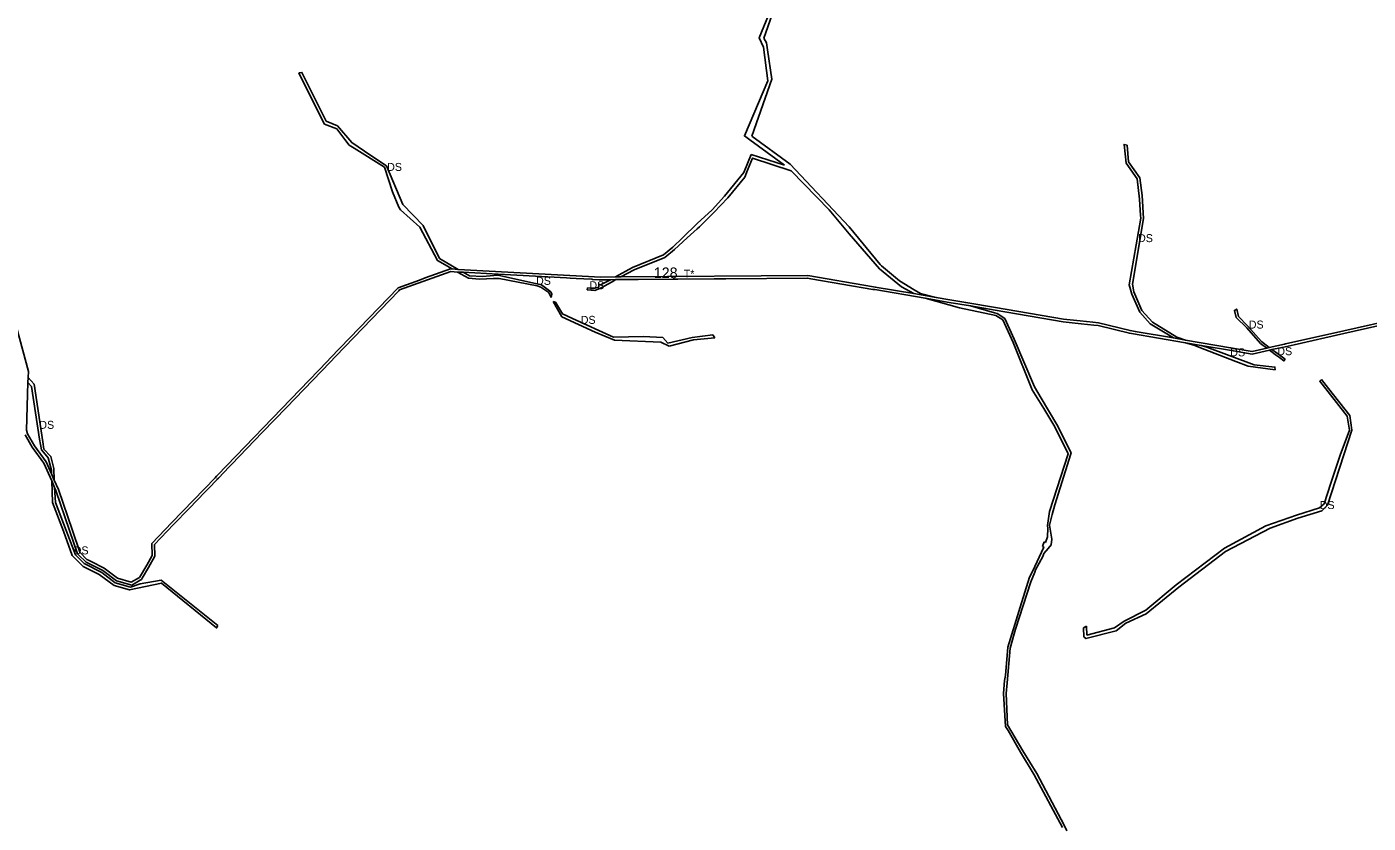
# Model space of a CAD drawing. Extents: x -477304 to -465641, y -1159113 to -1149285.
# Drawn here: x -473942 to -472433, y -1157333 to -1156437 of the extents above; entities that cross this region are included whole.
import ezdxf

# ---------------------------------------------------------------- set-up
doc = ezdxf.new("R2010")
doc.units = 0
for name, color, linetype in [('35', 7, 'Continuous'), ('4', 7, 'Continuous'), ('60', 7, 'Continuous')]:
    doc.layers.add(name, color=color, linetype=linetype)

msp = doc.modelspace()

# ---------------------------------------------------------------- linework, layer by layer
at = {"layer": '35'}
for p, q in [((-473110, -1156455.6), (-473113, -1156450.3)), ((-473113.4, -1156460.2), (-473108.3, -1156498)), ((-473108.9, -1156463.4), (-473110, -1156455.6)), ((-473635.9, -1156489), (-473624.1, -1156512.7)), ((-473624.1, -1156512.7), (-473607, -1156546.9)), ((-473592.2, -1156548.8), (-473604.9, -1156543.6)), ((-473573.4, -1156574), (-473539.6, -1156595.2)), ((-473083.2, -1156591.9), (-473126.3, -1156560.3)), ((-473127.3, -1156580.9), (-473135.4, -1156601.2)), ((-473089.8, -1156593.1), (-473127.3, -1156580.9)), ((-473539.6, -1156595.2), (-473530.3, -1156623)), ((-473519, -1156637.3), (-473537.3, -1156593.7)), ((-473135.4, -1156601.2), (-473157.2, -1156627.9)), ((-473134.4, -1156606.7), (-473131.2, -1156598.8)), ((-473016.9, -1156662.3), (-473083.2, -1156591.9)), ((-473530.3, -1156623), (-473523.5, -1156640.4)), ((-473523.5, -1156640.4), (-473521.5, -1156643.1)), ((-473521.5, -1156643.1), (-473499.7, -1156662.7)), ((-473199.2, -1156674.7), (-473188, -1156664.6)), ((-473188, -1156664.6), (-473185.3, -1156662.2)), ((-472689.2, -1156652.8), (-472702.3, -1156727.7)), ((-473456.6, -1156710.2), (-473477.5, -1156698.1)), ((-473463.2, -1156709.8), (-473456.6, -1156710.2)), ((-473260.5, -1156708.3), (-473279.9, -1156718.8)), ((-473273.7, -1156718.8), (-473258.8, -1156710.6)), ((-473258.8, -1156710.6), (-473224.4, -1156696.7)), ((-472960.3, -1156723.1), (-472980.5, -1156706.4)), ((-473450.9, -1156713.5), (-473457.3, -1156713.2)), ((-473457.3, -1156713.2), (-473444.9, -1156720.2)), ((-473444.9, -1156720.2), (-473432.7, -1156721.3)), ((-473432.7, -1156721.3), (-473416.8, -1156720.6)), ((-473416.8, -1156720.6), (-473410.7, -1156720.4)), ((-473410.7, -1156720.4), (-473367.9, -1156728.9)), ((-473285.5, -1156721.9), (-473296.4, -1156727.8)), ((-473279.3, -1156721.8), (-473285.5, -1156721.9)), ((-473283.6, -1156724.2), (-473279.3, -1156721.8)), ((-473279.9, -1156718.8), (-473273.7, -1156718.8)), ((-472943.9, -1156733.2), (-472960.3, -1156723.1)), ((-473367.9, -1156728.9), (-473363.5, -1156730.1)), ((-473363.5, -1156730.1), (-473354.5, -1156736.1)), ((-473352.5, -1156735.3), (-473362.8, -1156727.8)), ((-473354.5, -1156736.1), (-473352.1, -1156742)), ((-473351.2, -1156738.2), (-473352.5, -1156735.3)), ((-473352.1, -1156742), (-473351.2, -1156738.2)), ((-473311.2, -1156731), (-473311.5, -1156733.4)), ((-473307.5, -1156731.2), (-473311.2, -1156731)), ((-472958.3, -1156729.7), (-472944.1, -1156737.5)), ((-472944.1, -1156737.5), (-472919, -1156741.8)), ((-472936.7, -1156737.5), (-472943.9, -1156733.2)), ((-472919, -1156741.8), (-472936.7, -1156737.5)), ((-472702.3, -1156727.7), (-472699, -1156738.1)), ((-473349.7, -1156746.5), (-473340.1, -1156763.6)), ((-473347.2, -1156747.1), (-473349.7, -1156746.5)), ((-472931.6, -1156742.7), (-472892.8, -1156753.6)), ((-472892.8, -1156753.6), (-472852, -1156762.2)), ((-472853.5, -1156759), (-472880.6, -1156751.4)), ((-473340.1, -1156763.6), (-473302.5, -1156780.8)), ((-472850.7, -1156759.7), (-472853.5, -1156759)), ((-472841.8, -1156765.3), (-472850.7, -1156759.7)), ((-472831.4, -1156788.7), (-472841.8, -1156765.3)), ((-473302.5, -1156780.8), (-473280.7, -1156789.8)), ((-473248.2, -1156785.9), (-473281.9, -1156786.3)), ((-473226.4, -1156787), (-473248.2, -1156785.9)), ((-473170.2, -1156783.9), (-473193.5, -1156786.7)), ((-473167.9, -1156787.2), (-473170.2, -1156783.9)), ((-473280.7, -1156789.8), (-473228.7, -1156792.1)), ((-473228.7, -1156792.1), (-473219.5, -1156796.5)), ((-473220.7, -1156793.2), (-473226.4, -1156787)), ((-473193.5, -1156786.7), (-473220.7, -1156793.2)), ((-473219.5, -1156796.5), (-473192.2, -1156789.3)), ((-473192.2, -1156789.3), (-473167.9, -1156787.2)), ((-472652.3, -1156787.4), (-472638.8, -1156789.7)), ((-472638.8, -1156789.7), (-472648.5, -1156786.3)), ((-472621.3, -1156795.7), (-472638.9, -1156792.7)), ((-472638.9, -1156792.7), (-472628.4, -1156795.7)), ((-472628.4, -1156795.7), (-472624, -1156797.6)), ((-472624, -1156797.6), (-472582.3, -1156814)), ((-472615, -1156797.9), (-472621.3, -1156795.7)), ((-472554.5, -1156793.5), (-472547.5, -1156798.8)), ((-472544.8, -1156798.2), (-472553.5, -1156791.4)), ((-472547.5, -1156798.8), (-472544.8, -1156798.2)), ((-472541.6, -1156800.5), (-472544.3, -1156801.1)), ((-472544.3, -1156801.1), (-472536.4, -1156807.1)), ((-472535.4, -1156805), (-472541.6, -1156800.5)), ((-472582.3, -1156814), (-472568.4, -1156819)), ((-472526.9, -1156811.2), (-472535.4, -1156805)), ((-472568.4, -1156819), (-472538.1, -1156823.3)), ((-473940.1, -1156831.8), (-473940.3, -1156837.6)), ((-473940.3, -1156837.6), (-473936.4, -1156842)), ((-473933.5, -1156839.4), (-473940.1, -1156831.8)), ((-472478, -1156844.1), (-472485.9, -1156834.1)), ((-472783.4, -1156884.8), (-472801.2, -1156855.1)), ((-472479.2, -1156975.3), (-472451.7, -1156890.9)), ((-472454.3, -1156890.9), (-472464.8, -1156919.1)), ((-472464.8, -1156919.1), (-472475.5, -1156950.5)), ((-473910.7, -1156947.3), (-473911.4, -1156934)), ((-473913.9, -1156940.2), (-473910.7, -1156947.3)), ((-473910.3, -1156955.7), (-473913.6, -1156948.2)), ((-473913.6, -1156948.2), (-473912.8, -1156972.6)), ((-472791.7, -1156982.7), (-472794.1, -1156998.3)), ((-472791.6, -1156997.9), (-472790.3, -1156992.1)), ((-472790.3, -1156992.1), (-472789.1, -1156987.3)), ((-472789.1, -1156987.3), (-472788.7, -1156985.8)), ((-473886.8, -1157031.3), (-473897.3, -1157004.1)), ((-472794.1, -1157010.9), (-472796.4, -1157017.3)), ((-472794.1, -1156998.3), (-472793.8, -1157001.8)), ((-472793.8, -1157001.8), (-472794.1, -1157010.9)), ((-472799.3, -1157020.9), (-472799.7, -1157022)), ((-472797.8, -1157016.8), (-472799.3, -1157020.9)), ((-472798, -1157029.8), (-472793.4, -1157024.2)), ((-472796.4, -1157017.3), (-472797.8, -1157016.8)), ((-472646.4, -1157067.6), (-472593.9, -1157027.4)), ((-473890.5, -1157032), (-473878.2, -1157044.4)), ((-472807.4, -1157048.2), (-472799.1, -1157033.1)), ((-472799.1, -1157033.1), (-472798, -1157029.8)), ((-473878.2, -1157044.4), (-473860.1, -1157053.4)), ((-473842.1, -1157062.7), (-473857.4, -1157051)), ((-472812.9, -1157061.5), (-472808.4, -1157050.6)), ((-472808.4, -1157050.6), (-472807.4, -1157048.2)), ((-472750.1, -1157111.5), (-472753.4, -1157113.5)), ((-472753.4, -1157113.5), (-472753.2, -1157123.5)), ((-472749.8, -1157121.6), (-472750.1, -1157111.5)), ((-472718.8, -1157113.5), (-472749.8, -1157121.6)), ((-472841.4, -1157167), (-472842.4, -1157172.8)), ((-472840.6, -1157187.4), (-472839.5, -1157175.3)), ((-472838.9, -1157222.4), (-472840.6, -1157187.4)), ((-472821.6, -1157251.9), (-472838.9, -1157222.4)), ((-472805.8, -1157277.4), (-472821.6, -1157251.9)), ((-472809, -1157278.8), (-472777.1, -1157338.1))]:
    msp.add_line(p, q, dxfattribs=at)
for points in [[(-473113, -1156450.3), (-473103.5, -1156423.7), (-473101.2, -1156397.4)], [(-473107.7, -1156424.5), (-473118.2, -1156449.7), (-473113.4, -1156460.2)], [(-473126.3, -1156560.3), (-473104, -1156496.4), (-473108.9, -1156463.4)], [(-473604.9, -1156543.6), (-473632.3, -1156488.8), (-473635.9, -1156489)], [(-473108.3, -1156498), (-473134.7, -1156560.2), (-473128.5, -1156564.4), (-473089.8, -1156593.1)], [(-473607, -1156546.9), (-473593.2, -1156552.3), (-473584, -1156564.2)], [(-473537.3, -1156593.7), (-473554.7, -1156582.2), (-473576.2, -1156567.7), (-473592.2, -1156548.8)], [(-473584, -1156564.2), (-473579, -1156570.5), (-473573.4, -1156574)], [(-472704.5, -1156570.4), (-472707.8, -1156569.6), (-472705.6, -1156590.6), (-472693.2, -1156608.4), (-472690.4, -1156631.3), (-472689.4, -1156649.8), (-472689.2, -1156652.8)], [(-472687.4, -1156627.3), (-472690.2, -1156607.1), (-472702.8, -1156589.3), (-472704.5, -1156570.4)], [(-473131.2, -1156598.8), (-473125.5, -1156585), (-473082.2, -1156599.3)], [(-473082.2, -1156599.3), (-473039.3, -1156643.2), (-473017.1, -1156670.1), (-472983, -1156709.5), (-472958.3, -1156729.7)], [(-473185.3, -1156662.2), (-473169.1, -1156646.2), (-473153.4, -1156629.8), (-473134.4, -1156606.7)], [(-473157.2, -1156627.9), (-473170.9, -1156643.3), (-473187.9, -1156658.6)], [(-472648.5, -1156786.3), (-472675.9, -1156769.6), (-472687.8, -1156756.5), (-472696.8, -1156735.3), (-472698.4, -1156726.9), (-472686.1, -1156653.1), (-472687.4, -1156627.3)], [(-473477.5, -1156698.1), (-473496, -1156660.8), (-473519, -1156637.3)], [(-473499.7, -1156662.7), (-473480, -1156700.3), (-473463.2, -1156709.8)], [(-473187.9, -1156658.6), (-473204.4, -1156674.6), (-473215.4, -1156685.2), (-473225.9, -1156694), (-473260.5, -1156708.3)], [(-472980.5, -1156706.4), (-472982, -1156704.8), (-473016.9, -1156662.3)], [(-473224.4, -1156696.7), (-473213.5, -1156687.7), (-473199.2, -1156674.7)], [(-473429.1, -1156718.4), (-473444, -1156717.5), (-473450.9, -1156713.5)], [(-473362.8, -1156727.8), (-473411.9, -1156716.9), (-473429.1, -1156718.4)], [(-473311.5, -1156733.4), (-473307.2, -1156733.6), (-473303.1, -1156733.8), (-473296.7, -1156731.4), (-473283.6, -1156724.2)], [(-473298.4, -1156730.1), (-473302.9, -1156731.5), (-473307.5, -1156731.2)], [(-473296.4, -1156727.8), (-473298.4, -1156726.7), (-473298.6, -1156729.6), (-473298.4, -1156730.1)], [(-472699, -1156738.1), (-472690.1, -1156758.5), (-472678.6, -1156771.3), (-472652.3, -1156787.4)], [(-473281.9, -1156786.3), (-473327.9, -1156765.6), (-473339.3, -1156760.4), (-473347.2, -1156747.1)], [(-472880.6, -1156751.4), (-472904.4, -1156747.4), (-472931.6, -1156742.7)], [(-472553.5, -1156791.4), (-472569, -1156773.8), (-472579.4, -1156763.2), (-472581.2, -1156754.8), (-472583.8, -1156756.3), (-472581.8, -1156764.4)], [(-472852, -1156762.2), (-472844.1, -1156767), (-472832.6, -1156792.5), (-472811.1, -1156845.7)], [(-472581.8, -1156764.4), (-472569.9, -1156776), (-472554.5, -1156793.5)], [(-472801.2, -1156855.1), (-472808.7, -1156842.5), (-472831.4, -1156788.7)], [(-472538.1, -1156823.3), (-472538.3, -1156820.2), (-472561.6, -1156817.7), (-472615, -1156797.9)], [(-472536.4, -1156807.1), (-472533.3, -1156809.4), (-472528.2, -1156813.1), (-472526.9, -1156811.2)], [(-473936.4, -1156842), (-473927.5, -1156901.3), (-473925.1, -1156913.1), (-473923, -1156915.7), (-473917.7, -1156922.3), (-473914, -1156936.2), (-473913.9, -1156940.2)], [(-473922.3, -1156912.4), (-473923.7, -1156904.1), (-473933.5, -1156839.4)], [(-472811.1, -1156845.7), (-472798.2, -1156866.7), (-472785.7, -1156887.4), (-472770.6, -1156917.5), (-472791.7, -1156982.7)], [(-472485.9, -1156834.1), (-472487.8, -1156835.8), (-472457.2, -1156875.5), (-472454.3, -1156890.9)], [(-472451.7, -1156890.9), (-472454.2, -1156874.4), (-472478, -1156844.1)], [(-472788.7, -1156985.8), (-472785.7, -1156975.2), (-472767.7, -1156917.8), (-472767.4, -1156916.7), (-472783.4, -1156884.8)], [(-473911.4, -1156934), (-473914.7, -1156920.7), (-473922.3, -1156912.4)], [(-472475.5, -1156950.5), (-472482.8, -1156973.9), (-472488.2, -1156978.5), (-472514, -1156986.6), (-472548.5, -1156998.7), (-472595, -1157023.7)], [(-473897.3, -1157004.1), (-473909.5, -1156972.4), (-473910.3, -1156955.7)], [(-473912.8, -1156972.6), (-473900.3, -1157004.7), (-473890.5, -1157032)], [(-472593.9, -1157027.4), (-472543.8, -1157001.3), (-472512.6, -1156990.1), (-472485.6, -1156981.7), (-472479.2, -1156975.3)], [(-472793.4, -1157024.2), (-472789.8, -1157020), (-472789.2, -1157013.6), (-472791.6, -1156997.9)], [(-472799.7, -1157022), (-472798.2, -1157022.5), (-472811, -1157049.9)], [(-472595, -1157023.7), (-472649.3, -1157065), (-472683.3, -1157093.6), (-472707.8, -1157105.7), (-472718.8, -1157113.5)], [(-473857.4, -1157051), (-473877.3, -1157041), (-473886.8, -1157031.3)], [(-473860.1, -1157053.4), (-473843.3, -1157065.7), (-473826.1, -1157070.7), (-473790.2, -1157063.1), (-473728.3, -1157113.4), (-473726.7, -1157110.7)], [(-472811, -1157049.9), (-472814.2, -1157056.5), (-472824.8, -1157090)], [(-473814.1, -1157063.9), (-473825, -1157067.7), (-473842.1, -1157062.7)], [(-473726.7, -1157110.7), (-473790.5, -1157059.7), (-473814.1, -1157063.9)], [(-472831.6, -1157120.1), (-472829.9, -1157114.7), (-472812.9, -1157061.5)], [(-472716.8, -1157116.6), (-472705.8, -1157108.1), (-472683, -1157097.8), (-472646.4, -1157067.6)], [(-472824.8, -1157090), (-472838.5, -1157135.3), (-472841.4, -1157167)], [(-472753.2, -1157123.5), (-472750.8, -1157125.5), (-472716.8, -1157116.6)], [(-472839.5, -1157175.3), (-472836, -1157136.4), (-472831.6, -1157120.1)], [(-472842.4, -1157172.8), (-472843.3, -1157187.2), (-472841.2, -1157224.4), (-472838.1, -1157228.8)], [(-472838.1, -1157228.8), (-472824.5, -1157253.2), (-472809, -1157278.8)], [(-472772.2, -1157341.6), (-472775.2, -1157335.3), (-472805.8, -1157277.4)]]:
    msp.add_lwpolyline(points, dxfattribs=at)
at = {"layer": '4'}
for points in [[(-472397.4, -1156765.2), (-472460.9, -1156779.4), (-472526.5, -1156794.1), (-472527.6, -1156794.3), (-472544.8, -1156798.2), (-472547.5, -1156798.8), (-472563.9, -1156802.5), (-472588.1, -1156798.3), (-472638.8, -1156789.7), (-472652.3, -1156787.4), (-472695.3, -1156780), (-472701.2, -1156779), (-472736.6, -1156770.4), (-472743, -1156769.7), (-472757.3, -1156768.2), (-472775.9, -1156766.3), (-472852.3, -1156753.2), (-472886, -1156747.5), (-472903.9, -1156744.4), (-472919, -1156741.8), (-472944.1, -1156737.5), (-472987.6, -1156730.1), (-472989.5, -1156729.8), (-473063.6, -1156717.1), (-473273.7, -1156718.8), (-473279.9, -1156718.8), (-473296.3, -1156719), (-473456.6, -1156710.2), (-473463.2, -1156709.8), (-473465.3, -1156709.7), (-473493.6, -1156719.8), (-473500.2, -1156722.2), (-473524.1, -1156730.8), (-473600.4, -1156810.1), (-473603.6, -1156813.4), (-473727.1, -1156941.6), (-473728.3, -1156942.9), (-473730, -1156944.6), (-473778.6, -1156995.1), (-473801.2, -1157018.6), (-473800.5, -1157032.2), (-473806.8, -1157042.8), (-473815, -1157056.7), (-473824.1, -1157062.2), (-473839.6, -1157057.7), (-473854.5, -1157046.3), (-473869.3, -1157038.9), (-473872.3, -1157037.4), (-473874, -1157036.5), (-473882, -1157028.4), (-473882, -1157028.3), (-473890.3, -1157004.1), (-473906.1, -1156957.8), (-473910.7, -1156947.3), (-473913.9, -1156940.2), (-473919.8, -1156926.8), (-473933, -1156908.6), (-473940.7, -1156895.2), (-473942.1, -1156891), (-473940.3, -1156837.6), (-473940.1, -1156831.8), (-473939.8, -1156825), (-473966.5, -1156726.5)], [(-473943.4, -1156896.5), (-473935.5, -1156910.2), (-473922.4, -1156928.3), (-473913.6, -1156948.2), (-473910.3, -1156955.7), (-473908.9, -1156958.9), (-473893.5, -1157004.1), (-473884.6, -1157030), (-473882.6, -1157032), (-473875.8, -1157038.9), (-473874.8, -1157039.5), (-473862.8, -1157045.5), (-473856.1, -1157048.9), (-473840.9, -1157060.4), (-473823.6, -1157065.4), (-473814, -1157059.6), (-473812.8, -1157058.9), (-473812, -1157057.5), (-473804.9, -1157045.5), (-473797.5, -1157032.9), (-473798.1, -1157019.7), (-473776.5, -1156997.2), (-473759.2, -1156979.3), (-473741, -1156960.4), (-473736.9, -1156956.2), (-473727.9, -1156946.8), (-473727.8, -1156946.7), (-473726.1, -1156944.9), (-473714.1, -1156932.4), (-473711.4, -1156929.7), (-473676.5, -1156893.4), (-473649.6, -1156865.5), (-473610.4, -1156824.7), (-473600.7, -1156814.7), (-473594.4, -1156808.2), (-473523.4, -1156734.4), (-473522.4, -1156733.3), (-473475.2, -1156716.4), (-473464.9, -1156712.7), (-473457.3, -1156713.2), (-473450.9, -1156713.5), (-473411.6, -1156715.7), (-473334.8, -1156719.9), (-473330.5, -1156720.1), (-473323.8, -1156720.5), (-473315.3, -1156720.9), (-473306.4, -1156721.4), (-473305.6, -1156721.5), (-473297.9, -1156721.9), (-473296.4, -1156722), (-473285.5, -1156721.9), (-473279.3, -1156721.8), (-473254.2, -1156721.6), (-473214.7, -1156721.3), (-473209.8, -1156721.3), (-473168.8, -1156721), (-473155.5, -1156720.9), (-473063.8, -1156720.1), (-473060.1, -1156720.8), (-472990.4, -1156732.7), (-472988.3, -1156733), (-472931.6, -1156742.7), (-472904.4, -1156747.4), (-472880.6, -1156751.4), (-472852.9, -1156756.1), (-472776.4, -1156769.2), (-472756.1, -1156771.4), (-472742, -1156772.9), (-472737.1, -1156773.4), (-472701.8, -1156782), (-472699.7, -1156782.3), (-472638.9, -1156792.7), (-472621.3, -1156795.7), (-472585, -1156801.9), (-472563.9, -1156805.5), (-472544.3, -1156801.1), (-472541.6, -1156800.5), (-472530.3, -1156798), (-472516.7, -1156795), (-472460.9, -1156782.5), (-472395.9, -1156767.9)]]:
    msp.add_lwpolyline(points, dxfattribs=at)

# ---------------------------------------------------------------- texts
at = {"layer": '35'}
for p in [(-473536.5, -1156599.5), (-472692.2, -1156679.6), (-473369.1, -1156727.6), (-473309.1, -1156732.6), (-473318.8, -1156771.5), (-472567.7, -1156776.8), (-472588.5, -1156808), (-472535.6, -1156806.8), (-473927.6, -1156889.6), (-472487.9, -1156979.8), (-473888.9, -1157030.8)]:
    msp.add_text('DS', height=9, dxfattribs=at).set_placement(p)
at = {"layer": '4'}
msp.add_text('T*', height=9, dxfattribs=at).set_placement((-473203, -1156719.7))
at = {"layer": '60'}
msp.add_text('128', height=12, dxfattribs=at).set_placement((-473236.7, -1156720.1))

doc.saveas('drawing.dxf')
